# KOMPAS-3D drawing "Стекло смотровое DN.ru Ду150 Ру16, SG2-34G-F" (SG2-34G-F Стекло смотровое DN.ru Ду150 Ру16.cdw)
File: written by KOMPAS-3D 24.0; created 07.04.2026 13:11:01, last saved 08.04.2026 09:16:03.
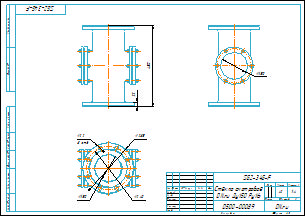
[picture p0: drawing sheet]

Document properties: Автор: Main; Форматы листов документа: A3; Полное имя файла: SG2-34G-F Стекло смотровое DN.ru Ду150 Ру16.m3d; Масса: 42; Наименование: Стекло смотровое DN.ru Ду150 Ру16; Количество листов документа: 1; Примечание: D500-00089

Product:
- Part/product: Стекло смотровое DN.ru Ду150 Ру16  | designation SG2-34G-F
    Масса: 42
    Раздел спецификации: Прочие изделия
    Примечание: D500-00089

Views: Вид 1, Снизу, Проекционный вид 2
Referenced files in D:\DN.ru Аутсерс\Стекло смотровое DN.ru\Стекло смотровое DN.ru SG2-34G-F тип В ГОСТ 21836-2021 Ду100 Ру16, углеродистая сталь, фланцевое\: SG2-34G-F тип В Стекло смотровое DN.ru Ду100 Ру16.m3d, SG2-34G-F тип ВСтекло смотровое DN.ru Ду100 Ру16.cdw
Referenced files in D:\DN.ru Аутсерс\Стекло смотровое DN.ru\SG2-34G-F Стекло смотровое DN.ru Ду150 Ру16\: SG2-34G-F Стекло смотровое DN.ru Ду150 Ру16.m3d
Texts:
  SG2-34G-F
  Стекло смотровое
  DN.ru Ду150 Ру16
  Стекло смотровое DN.ru Ду150 Ру16
  SG2-34G-F Стекло смотровое DN.ru Ду150 Ру16
Dimensions and other numbers on the sheet: 0; 3; 2; 4; 450; 22; 285; 240; 150; 8 отв.; 1:4; 1; 42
